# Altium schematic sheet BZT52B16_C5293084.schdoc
size 127 x 101 mm
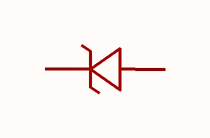
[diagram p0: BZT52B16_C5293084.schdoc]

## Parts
U?  bzt52b16_c5293084  [SOD-123_L2.8-W1.6-LS3.7-RD]  (value not drawn)

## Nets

Not connected (* = marked no-connect by the designer): U? 1(C) 2(A)

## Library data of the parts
U? = bzt52b16_c5293084: 二极管配置:1个独立式;稳压值(标称值):16V;稳压值(范围值):15.68V~16.32V;耗散功率(Pd):500mW;; Manufacturer: CJ(江苏长电/长晶); AddInBom: yes; ModelId: 73858e86c18848f5a81710cfe7352ee5; ModelTransform: 145.669,70.3249,0,0,0,0,0,0,0; Diode Configuration: 1个独立式; Zener Voltage(Nom): 16V; Reverse Leakage Current (Ir): 100nA@11.2V; Pd - Power Dissipation: 500mW; Impedance(Zzt): 40Ω; Impedance(Zzk): 200Ω; Operating Junction Temperature Range: -55℃~+150℃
